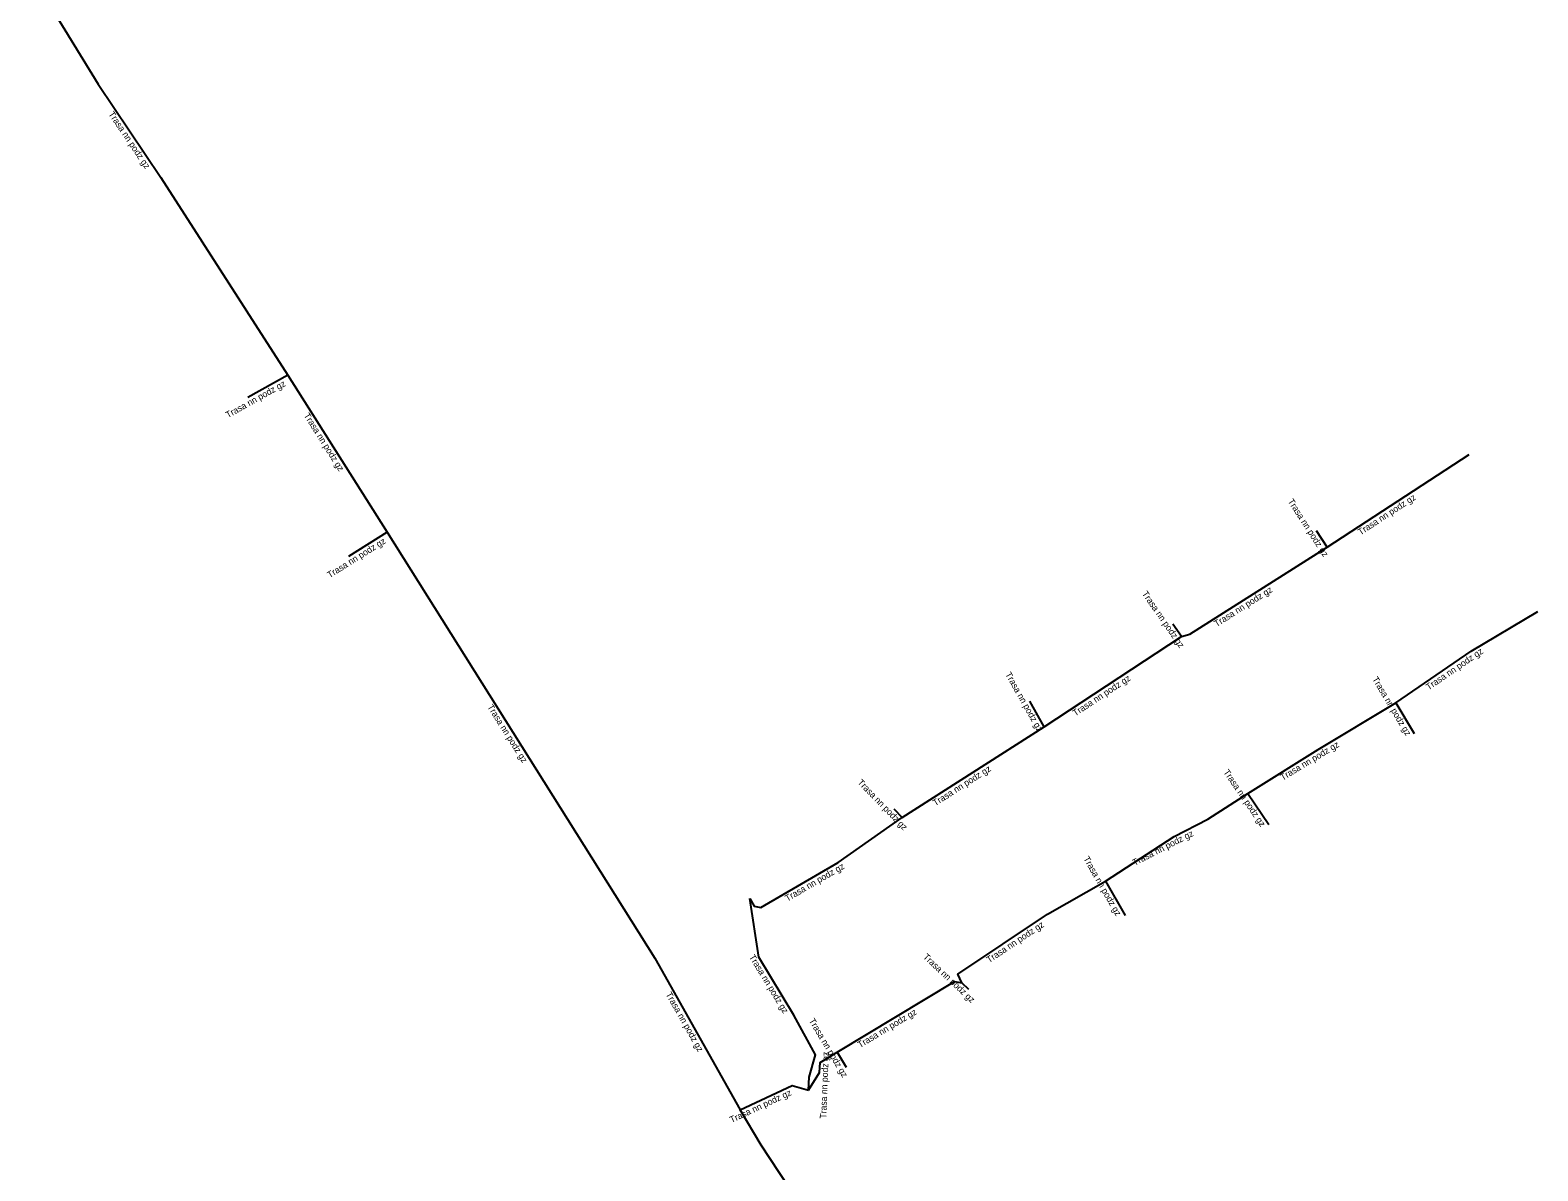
# Model space of a CAD drawing. Extents: x -467803 to -467116, y -1117596 to -1116713.
# Drawn here: x -467469.5 to -467353.1, y -1116954.2 to -1116866.1 of the extents above; entities that cross this region are included whole.
import ezdxf

# ---------------------------------------------------------------- set-up
doc = ezdxf.new("R2010")
doc.units = 0
doc.layers.add('Popiskový text - Ostatní atributy Trasy', color=7, linetype='Continuous')
doc.layers.add('Spojnice NN', color=7, linetype='Continuous')

msp = doc.modelspace()

# ---------------------------------------------------------------- linework, layer by layer
at = {"layer": 'Spojnice NN'}
for points in [[(-467466.32, -1116858.88), (-467469.49, -1116861.38), (-467468.89, -1116862.61), (-467464.24, -1116870.24), (-467459.39, -1116877.46), (-467449.59, -1116892.71)], [(-467449.59, -1116892.71), (-467452.69, -1116894.45)], [(-467449.59, -1116892.71), (-467441.93, -1116904.85)], [(-467369.36, -1116906.01), (-467358.39, -1116898.85)], [(-467441.93, -1116904.85), (-467444.9, -1116906.72)], [(-467441.93, -1116904.85), (-467421.26, -1116937.74)], [(-467369.36, -1116906.01), (-467370.17, -1116904.75)], [(-467380.6, -1116912.91), (-467379.95, -1116912.72), (-467369.36, -1116906.01)], [(-467364.06, -1116918.02), (-467358.24, -1116914.04), (-467353.09, -1116910.97)], [(-467380.6, -1116912.91), (-467381.26, -1116911.96)], [(-467391.2, -1116919.88), (-467380.6, -1116912.91)], [(-467391.2, -1116919.88), (-467392.31, -1116917.91)], [(-467375.47, -1116925.04), (-467370.05, -1116921.64), (-467364.06, -1116918.02)], [(-467364.06, -1116918.02), (-467362.65, -1116920.39)], [(-467402.16, -1116926.87), (-467391.2, -1116919.88)], [(-467386.46, -1116931.8), (-467381.17, -1116928.34), (-467378.58, -1116927.02), (-467375.47, -1116925.04)], [(-467375.47, -1116925.04), (-467373.85, -1116927.42)], [(-467402.16, -1116926.87), (-467402.78, -1116926.23)], [(-467413.93, -1116933.15), (-467413.6, -1116933.72), (-467413.09, -1116933.84), (-467407.1, -1116930.35), (-467402.16, -1116926.87)], [(-467397.57, -1116939.65), (-467397.88, -1116938.98), (-467390.94, -1116934.34), (-467386.46, -1116931.8)], [(-467386.46, -1116931.8), (-467384.95, -1116934.45)], [(-467409.41, -1116947.95), (-467409.35, -1116946.93), (-467408.87, -1116945.21), (-467410.53, -1116942.15), (-467413.23, -1116937.68), (-467413.93, -1116933.15)], [(-467421.26, -1116937.74), (-467414.68, -1116949.47)], [(-467407.19, -1116945.01), (-467398.12, -1116939.56), (-467397.57, -1116939.65)], [(-467397.57, -1116939.65), (-467397.05, -1116940.14)], [(-467409.41, -1116947.95), (-467408.54, -1116946.58), (-467408.51, -1116945.8), (-467407.19, -1116945.01)], [(-467407.19, -1116945.01), (-467406.5, -1116946.17)], [(-467414.68, -1116949.47), (-467410.66, -1116947.59), (-467409.41, -1116947.95)], [(-467399.6, -1116972.63), (-467413.05, -1116952.2), (-467414.68, -1116949.47)]]:
    msp.add_lwpolyline(points, dxfattribs=at)

# ---------------------------------------------------------------- texts
at = {"layer": 'Popiskový text - Ostatní atributy Trasy'}
for rotation, p in [(303.891, (-467463.47, -1116872.55)), (29.3051, (-467454.22, -1116896.05)), (302.2508, (-467448.39, -1116895.83)), (302.6799, (-467372.42, -1116902.46)), (33.1359, (-467366.78, -1116905.1)), (32.1957, (-467446.36, -1116908.41)), (32.3516, (-467377.89, -1116912.18)), (304.7014, (-467383.68, -1116909.6)), (34.3662, (-467361.52, -1116917.07)), (299.3992, (-467394.23, -1116915.82)), (33.3204, (-467388.8, -1116919.08)), (300.75, (-467365.9, -1116916.19)), (302.1477, (-467434.22, -1116918.34)), (31.1463, (-467372.79, -1116924.05)), (32.5287, (-467399.61, -1116926.02)), (304.242, (-467377.39, -1116923.38)), (314.0906, (-467405.65, -1116924.21)), (27.0058, (-467384.22, -1116930.62)), (299.675, (-467388.2, -1116930.06)), (30.2267, (-467411.03, -1116933.39)), (33.7662, (-467395.45, -1116938.14)), (301.2195, (-467414.01, -1116937.65)), (316.7014, (-467400.59, -1116937.7)), (299.2756, (-467420.44, -1116940.53)), (30.9879, (-467405.42, -1116944.7)), (300.6337, (-467409.39, -1116942.57)), (87.7974, (-467408.03, -1116950.15)), (25.0644, (-467415.34, -1116950.49))]:
    msp.add_text('Trasa nn podz gz', height=0.5, rotation=rotation, dxfattribs=at).set_placement(p)

doc.saveas('drawing.dxf')
